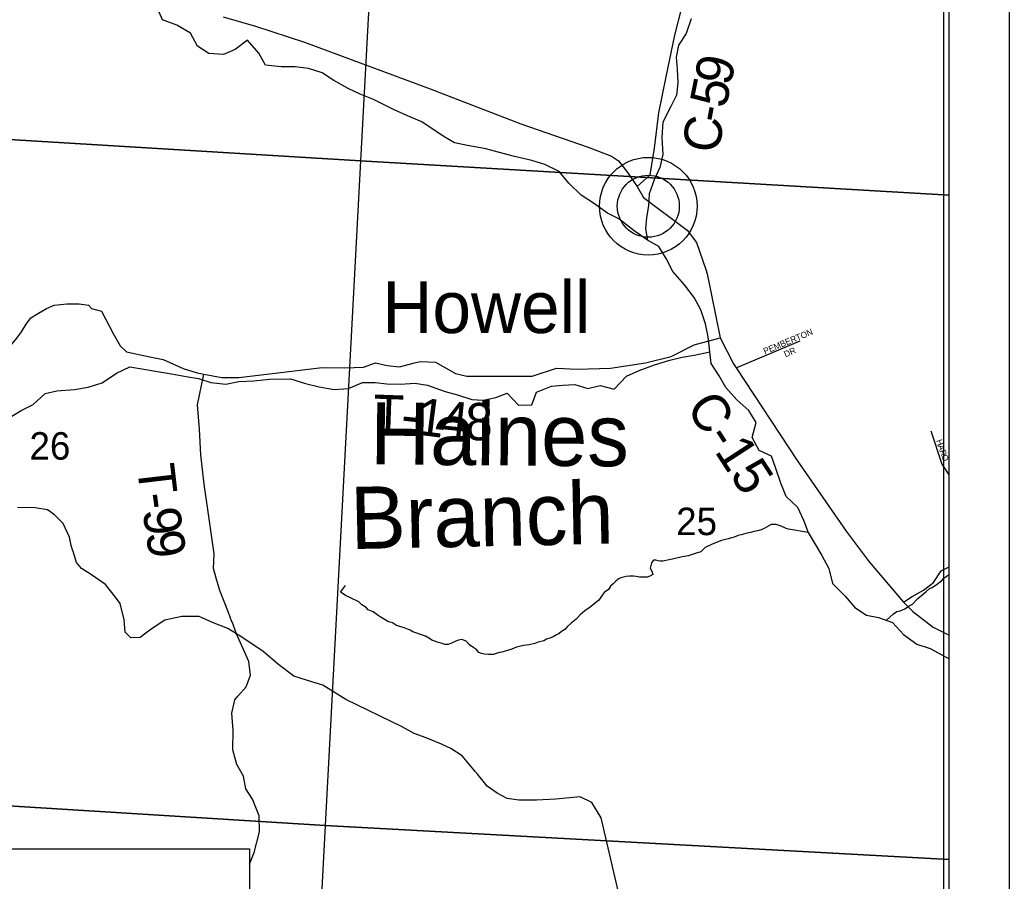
# Model space of a CAD drawing. Extents: x 0 to 34, y 0 to 22.
# Drawn here: x 7.493 to 9, y 16.725 to 18.037 of the extents above; entities that cross this region are included whole.
import ezdxf

# ---------------------------------------------------------------- set-up
doc = ezdxf.new("R2010")
doc.units = 0
for name, color, linetype in [('GM_X_County', 7, 'Continuous'), ('GM_X_County_Road', 7, 'Continuous'), ('GM_X_County_Road_Text', 7, 'Continuous'), ('GM_X_Minor_River', 7, 'Continuous'), ('GM_X_Minor_River_Text', 7, 'Continuous'), ('GM_X_Section', 7, 'Continuous'), ('GM_X_Section_Text', 7, 'Continuous'), ('GM_X_Township', 7, 'Continuous'), ('GM_X_Township_Road', 7, 'Continuous'), ('GM_X_Township_Road_Text', 7, 'Continuous'), ('GM_X_Township_ROW', 7, 'Continuous'), ('GM_X_Township_Subdivision', 7, 'Continuous'), ('GM_X_Township_Subdivision_Text', 7, 'Continuous'), ('GM_X_Unincorporated', 7, 'Continuous'), ('GM_X_Unincorporated_Location', 7, 'Continuous'), ('GM_X_Unincorporated_Text', 7, 'Continuous'), ('SH_Data', 7, 'Continuous'), ('SH_Text', 7, 'Continuous')]:
    doc.layers.add(name, color=color, linetype=linetype)

msp = doc.modelspace()

# ---------------------------------------------------------------- linework, layer by layer
at = {"layer": 'GM_X_County'}
msp.add_lwpolyline([(8.9084, 15.63), (8.9084, 20.8908), (2.1084, 20.8908), (2.1084, 19.9847)], dxfattribs=at)
at = {"layer": 'GM_X_County_Road'}
for points in [[(8.4331, 17.7828), (8.4533, 17.8008), (8.4598, 17.8414), (8.4662, 17.895), (8.4776, 17.9502), (8.4905, 18.0135), (8.5019, 18.0573)], [(7.8026, 18.0416), (7.8521, 18.0274), (7.9265, 18.0026), (8.1178, 17.9317), (8.256, 17.8785), (8.3587, 17.843), (8.3941, 17.8289), (8.4047, 17.8218), (8.4189, 17.804), (8.4222, 17.7991), (8.4331, 17.7828), (8.4431, 17.7661), (8.5093, 17.7164), (8.5235, 17.6974), (8.5378, 17.6565), (8.54, 17.65), (8.5595, 17.5525)], [(8.5595, 17.5525), (8.5802, 17.5127), (8.5843, 17.5065), (8.6772, 17.3658), (8.7517, 17.258), (8.7867, 17.2113), (8.8392, 17.1498), (8.8533, 17.1354), (8.8844, 17.1119), (8.9084, 17.0997)]]:
    msp.add_lwpolyline(points, dxfattribs=at)
at = {"layer": 'GM_X_Minor_River'}
for points in [[(8.6774, 17.2946), (8.6604, 17.3107), (8.6521, 17.3313), (8.6439, 17.3549), (8.6379, 17.3724), (8.619, 17.3808), (8.6085, 17.4007), (8.6146, 17.4235), (8.6033, 17.4418), (8.5852, 17.4578), (8.5686, 17.4769), (8.5581, 17.4944), (8.546, 17.5135), (8.5438, 17.531), (8.5417, 17.5538), (8.5372, 17.5736), (8.5305, 17.5949), (8.5199, 17.614), (8.5056, 17.6331), (8.4875, 17.6537), (8.4777, 17.6735), (8.4665, 17.6918), (8.4491, 17.701), (8.4287, 17.7155), (8.4053, 17.7338), (8.3879, 17.7422), (8.3668, 17.7575), (8.3479, 17.7698), (8.329, 17.7881), (8.3147, 17.8056), (8.2928, 17.8163), (8.2731, 17.8225), (8.2466, 17.8287), (8.2292, 17.8333), (8.2027, 17.8402), (8.1725, 17.8457), (8.1551, 17.8495), (8.1377, 17.8595), (8.1052, 17.8816), (8.0833, 17.8908), (8.0621, 17.9), (8.0319, 17.9154), (8.0115, 17.9238), (7.9933, 17.9322), (7.9714, 17.9445), (7.9533, 17.9559), (7.9329, 17.9628), (7.9124, 17.9652), (7.8912, 17.9653), (7.867, 17.9676), (7.8572, 17.9859), (7.8399, 18.0057), (7.8209, 17.9914), (7.8034, 17.9838), (7.7807, 17.9854), (7.7634, 17.9969), (7.7528, 18.0167), (7.7324, 18.0289), (7.7105, 18.0366), (7.7, 18.0602)], [(8.5156, 18.0382), (8.5079, 18.0162), (8.4965, 17.998), (8.4926, 17.9798), (8.494, 17.9616), (8.4955, 17.941), (8.4931, 17.922), (8.4847, 17.9046), (8.4725, 17.8811), (8.4709, 17.8575), (8.4723, 17.8317), (8.4677, 17.8119), (8.4593, 17.7929), (8.4516, 17.7717), (8.4508, 17.7534), (8.4477, 17.7359), (8.4461, 17.7185), (8.4491, 17.701)], [(7.4718, 17.4276), (7.4953, 17.442), (7.5135, 17.4511), (7.5318, 17.4677), (7.5492, 17.4715), (7.5765, 17.4736), (7.5969, 17.4774), (7.6182, 17.4841), (7.6402, 17.4985), (7.6607, 17.5083), (7.7242, 17.4975), (7.7462, 17.4936), (7.7651, 17.4905), (7.784, 17.4843), (7.8067, 17.482), (7.8264, 17.4857), (7.8492, 17.4871), (7.8734, 17.4893), (7.9052, 17.49), (7.9279, 17.483), (7.9491, 17.4776), (7.9718, 17.4737), (7.9938, 17.4752), (8.015, 17.4842), (8.034, 17.4842), (8.0521, 17.4826), (8.0726, 17.4817), (8.0945, 17.4832), (8.1142, 17.4801), (8.1407, 17.4709), (8.1596, 17.4655), (8.1815, 17.4585), (8.199, 17.4577), (8.2179, 17.4614), (8.2353, 17.4682), (8.2527, 17.4499), (8.2731, 17.4506), (8.28, 17.4696), (8.3028, 17.4786), (8.3202, 17.4801), (8.3384, 17.4815), (8.3581, 17.4754), (8.377, 17.4799), (8.3982, 17.4745), (8.4172, 17.4942), (8.4362, 17.5025), (8.4597, 17.5115), (8.4832, 17.5183), (8.5021, 17.5228), (8.5203, 17.5258), (8.5438, 17.531), (8.5423, 17.5302)], [(8.6774, 17.2946), (8.6869, 17.2748), (8.6936, 17.2558), (8.7148, 17.2208), (8.7254, 17.201), (8.7306, 17.1782), (8.7503, 17.1592), (8.7647, 17.1417), (8.7828, 17.1302), (8.801, 17.1264), (8.8222, 17.1188), (8.8388, 17.1005), (8.8592, 17.0861), (8.8796, 17.0792), (8.9038, 17.0663), (8.9084, 17.0636)], [(8.6936, 17.2558), (8.6637, 17.261), (8.6604, 17.2622), (8.6525, 17.2657), (8.6449, 17.2681), (8.6374, 17.2679), (8.627, 17.262), (8.6224, 17.2601), (8.6164, 17.2587), (8.6114, 17.2573), (8.6057, 17.2559), (8.5989, 17.2544), (8.5916, 17.2523), (8.5874, 17.2512), (8.5813, 17.249), (8.5775, 17.2476), (8.5718, 17.2465), (8.5657, 17.2447), (8.5619, 17.2437), (8.5551, 17.2411), (8.5467, 17.2378), (8.5368, 17.233), (8.5302, 17.2267), (8.5218, 17.2238), (8.5157, 17.222), (8.5115, 17.2205), (8.502, 17.2188), (8.4979, 17.2177), (8.4914, 17.2163), (8.4872, 17.2152), (8.4823, 17.2142), (8.4724, 17.2125), (8.4686, 17.2125), (8.4652, 17.213), (8.4618, 17.2138), (8.4584, 17.2138), (8.4553, 17.2097), (8.4541, 17.2055), (8.4533, 17.2014), (8.4558, 17.1971), (8.4573, 17.1922), (8.4527, 17.1892), (8.4485, 17.1881), (8.4443, 17.1878), (8.4371, 17.1879), (8.4318, 17.1888), (8.4277, 17.1892), (8.4216, 17.1893), (8.4167, 17.1887), (8.4083, 17.1869), (8.4045, 17.1847), (8.401, 17.1817), (8.3968, 17.1776), (8.3926, 17.1742), (8.3894, 17.1693), (8.3833, 17.1645), (8.3798, 17.1604), (8.3748, 17.1528), (8.3617, 17.1424), (8.3537, 17.1364), (8.3467, 17.1305), (8.3402, 17.1241), (8.3329, 17.1178), (8.3267, 17.1122), (8.3232, 17.108), (8.3179, 17.1051), (8.314, 17.1017), (8.3102, 17.1003), (8.3056, 17.0969), (8.3018, 17.0955), (8.2953, 17.0937), (8.2911, 17.0911), (8.2824, 17.0889), (8.2774, 17.0867), (8.2687, 17.085), (8.2645, 17.0843), (8.26, 17.084), (8.2535, 17.0822), (8.2497, 17.0811), (8.2462, 17.08), (8.2424, 17.0782), (8.2272, 17.0739), (8.2238, 17.0732), (8.2185, 17.0718), (8.2143, 17.0703), (8.2071, 17.0701), (8.2006, 17.0705), (8.1961, 17.0714), (8.192, 17.0734), (8.1879, 17.078), (8.1845, 17.0803), (8.1781, 17.0846), (8.1729, 17.0904), (8.1662, 17.0928), (8.1612, 17.0918), (8.157, 17.0903), (8.1505, 17.0874), (8.1452, 17.0856), (8.1403, 17.0853), (8.1346, 17.0873), (8.1286, 17.0889)], [(8.8131, 17.1223), (8.824, 17.1319), (8.829, 17.1356), (8.8339, 17.1366), (8.8408, 17.1399), (8.8477, 17.1444), (8.8527, 17.1466), (8.8608, 17.1556), (8.8696, 17.1627), (8.8735, 17.166), (8.8788, 17.1705), (8.8826, 17.172), (8.8907, 17.1775), (8.8968, 17.1824), (8.9003, 17.1865), (8.9076, 17.1917), (8.9084, 17.1924)], [(8.1286, 17.0889), (8.1252, 17.0905), (8.1207, 17.0921), (8.117, 17.0944), (8.111, 17.098), (8.1034, 17.1004), (8.0963, 17.1032), (8.0914, 17.1048), (8.0876, 17.1071), (8.0827, 17.1091), (8.0771, 17.1111), (8.0665, 17.1143), (8.0606, 17.1182), (8.0568, 17.1194), (8.0534, 17.1206), (8.0493, 17.123), (8.0421, 17.1273), (8.0388, 17.1293), (8.0313, 17.1351), (8.0238, 17.1383), (8.0204, 17.1417), (8.0137, 17.1457), (8.0092, 17.1503), (7.9968, 17.1566), (7.9893, 17.1602), (7.9856, 17.1625), (7.9814, 17.1649), (7.9892, 17.1754)]]:
    msp.add_lwpolyline(points, dxfattribs=at)
at = {"layer": 'GM_X_Section'}
for p, q in [((8.9084, 17.7699), (8.9084, 18.7841)), ((8.9084, 16.7577), (8.9084, 17.7699)), ((8.9084, 15.7545), (8.9084, 16.7577))]:
    msp.add_line(p, q, dxfattribs=at)
for points in [[(6.9681, 18.8952), (8.0664, 18.8297), (8.012, 17.8219), (6.9079, 17.8893)], [(8.012, 17.8219), (7.9583, 16.8099), (6.8455, 16.8788), (6.9079, 17.8893)]]:
    msp.add_lwpolyline(points, close=True, dxfattribs=at)
for points in [[(8.9084, 18.7841), (8.0664, 18.8297), (8.012, 17.8219), (8.9084, 17.7699)], [(8.9084, 17.7699), (8.012, 17.8219), (7.9583, 16.8099), (8.9084, 16.7577)], [(6.8391, 16.7743), (6.8455, 16.8788), (7.9583, 16.8099), (7.9053, 15.8044), (6.7831, 15.8661), (6.795, 16.0591)], [(8.9084, 16.7577), (7.9583, 16.8099), (7.9053, 15.8044), (8.9084, 15.7545)]]:
    msp.add_lwpolyline(points, dxfattribs=at)
at = {"layer": 'GM_X_Township'}
msp.add_lwpolyline([(8.9084, 15.63), (8.9084, 20.8908), (5.9855, 20.8908)], dxfattribs=at)
at = {"layer": 'GM_X_Township_Road'}
for points in [[(7.8987, 17.5006), (7.9536, 17.5074), (7.9881, 17.5066), (8.0165, 17.5077), (8.0346, 17.5145), (8.0524, 17.5104), (8.0714, 17.5084), (8.0922, 17.5138), (8.1028, 17.5164), (8.1263, 17.5156), (8.1566, 17.4981), (8.174, 17.4943), (8.2733, 17.4939), (8.3104, 17.5061), (8.3418, 17.5049), (8.3926, 17.5064), (8.446, 17.5144), (8.485, 17.5239), (8.5202, 17.5417), (8.5595, 17.5525)], [(7.8161, 17.1201), (7.8108, 17.1343), (7.7979, 17.1674), (7.7923, 17.1864), (7.7881, 17.2012), (7.7892, 17.2233), (7.7809, 17.2804), (7.7737, 17.3298), (7.7688, 17.3743), (7.7665, 17.4135), (7.7638, 17.4504), (7.7733, 17.4972)], [(7.5739, 17.2281), (7.5714, 17.2363), (7.5688, 17.2489), (7.5589, 17.2694), (7.546, 17.2827), (7.535, 17.2904), (7.5165, 17.2934), (7.4896, 17.2938)], [(8.8392, 17.1498), (8.8524, 17.1586), (8.8695, 17.1681), (8.8782, 17.1746), (8.8846, 17.18), (8.8963, 17.1975), (8.9084, 17.2035)], [(7.8252, 17.0066), (7.8253, 17.0068), (7.8377, 17.0209), (7.8445, 17.0388), (7.8419, 17.0593), (7.823, 17.1018), (7.8162, 17.1198), (7.8161, 17.1201)], [(7.8426, 16.7509), (7.8499, 16.7683), (7.8582, 16.7999), (7.8578, 16.8246), (7.8472, 16.8497), (7.8374, 16.8657), (7.8339, 16.8847), (7.8237, 16.9026), (7.8177, 16.925), (7.818, 16.9543), (7.8158, 16.9806), (7.8203, 17.0011), (7.8252, 17.0066)], [(8.4101, 16.6863), (8.3786, 16.8213), (8.3642, 16.8445), (8.3464, 16.8533), (8.3093, 16.8499), (8.2798, 16.8484), (8.2533, 16.848), (8.2355, 16.851), (8.2199, 16.8587), (8.2048, 16.8697), (8.1904, 16.8872), (8.1865, 16.8919), (8.1843, 16.8946)]]:
    msp.add_lwpolyline(points, dxfattribs=at)
at = {"layer": 'GM_X_Township_ROW'}
for points in [[(7.3077, 17.4886), (7.3126, 17.4878), (7.3221, 17.483), (7.3363, 17.4783), (7.3886, 17.4783), (7.4052, 17.4831), (7.4195, 17.4902), (7.4313, 17.495), (7.448, 17.5069), (7.4612, 17.52), (7.4622, 17.5211), (7.4789, 17.5402), (7.4884, 17.5521), (7.4955, 17.5616), (7.5026, 17.5735), (7.5097, 17.583), (7.5216, 17.5901), (7.5335, 17.5973), (7.5454, 17.602), (7.5644, 17.6044), (7.5747, 17.6044)], [(7.5747, 17.6044), (7.5834, 17.6044), (7.5976, 17.602), (7.6024, 17.5973), (7.6172, 17.593), (7.6354, 17.5592), (7.646, 17.5402), (7.6555, 17.5311), (7.6695, 17.528), (7.6911, 17.5234), (7.7115, 17.5192), (7.7418, 17.5059), (7.7631, 17.4991), (7.7733, 17.4972), (7.8009, 17.4918), (7.8267, 17.4918), (7.8987, 17.5006)], [(8.1843, 16.8946), (8.1794, 16.9005), (8.1669, 16.9157), (8.1495, 16.9268), (8.1355, 16.9336), (8.112, 16.9432), (8.0934, 16.95), (8.0756, 16.9599), (7.9896, 17.0018), (7.9544, 17.0235), (7.9313, 17.0304), (7.9104, 17.0372), (7.8877, 17.0543), (7.8635, 17.0745), (7.8267, 17.0996), (7.823, 17.1018), (7.8097, 17.1095), (7.7866, 17.1187), (7.7661, 17.1282), (7.74, 17.1282), (7.7138, 17.1225), (7.693, 17.1088), (7.6847, 17.1028), (7.6763, 17.0959), (7.6623, 17.0955), (7.6536, 17.1039), (7.6521, 17.1229), (7.6457, 17.148), (7.6388, 17.1576), (7.6233, 17.1766), (7.6021, 17.1914), (7.5869, 17.2013), (7.5794, 17.2101), (7.5743, 17.2269), (7.5739, 17.2281)]]:
    msp.add_lwpolyline(points, dxfattribs=at)
at = {"layer": 'GM_X_Township_Subdivision'}
for points in [[(8.5843, 17.5065), (8.6816, 17.5479)], [(8.9009, 17.3554), (8.9007, 17.3556), (8.8981, 17.3595), (8.8812, 17.4102)], [(8.9084, 17.3438), (8.9009, 17.3554)]]:
    msp.add_lwpolyline(points, dxfattribs=at)
at = {"layer": 'GM_X_Unincorporated'}
for radius in [0.0744, 0.0472]:
    msp.add_circle((8.4503, 17.7529), radius, dxfattribs=at)
at = {"layer": 'GM_X_Unincorporated_Location'}
msp.add_line((8.4503, 17.7529), (8.4503, 17.7529), dxfattribs=at)
at = {"layer": 'SH_Data'}
for p, q in [((9, 21), (9, 14)), ((8.9, 20.9), (8.9, 14.1))]:
    msp.add_line(p, q, dxfattribs=at)
at = {"layer": 'SH_Text'}
msp.add_lwpolyline([(6.0532, 16.7743), (7.8426, 16.7743), (7.8426, 16.0591), (6.0532, 16.0591)], close=True, dxfattribs=at)

# ---------------------------------------------------------------- texts
at = {"layer": 'GM_X_County_Road_Text'}
for s, height, rotation, p in [('9', 0.0568, 78.1389, (8.5754, 17.9348)), ('5', 0.0568, 78.5958, (8.5685, 17.9006)), ('-', 0.0568, 79.7983, (8.5644, 17.8779)), ('C', 0.0568, 82.2918, (8.5582, 17.8323)), ('C-15', 0.05682, 303.0238, (8.5066, 17.4468))]:
    msp.add_text(s, height=height, rotation=rotation, dxfattribs=at).set_placement(p)
at = {"layer": 'GM_X_Minor_River_Text'}
for s, rotation, p in [('Haines', 359.5508, (8.0263, 17.3597)), ('Branch', 1.2147, (7.9972, 17.2306))]:
    msp.add_text(s, height=0.09469, rotation=rotation, dxfattribs=at).set_placement(p)
at = {"layer": 'GM_X_Section_Text'}
for s, p in [('26', (7.5077, 17.3669)), ('25', (8.4927, 17.2519))]:
    msp.add_text(s, height=0.04186, rotation=0, dxfattribs=at).set_placement(p)
at = {"layer": 'GM_X_Township_Road_Text'}
for s, rotation, p in [('T', 357.9714, (8.0305, 17.4094)), ('1', 352.6917, (8.0948, 17.4055)), ('4', 354.1461, (8.1311, 17.4009)), ('8', 358.4968, (8.1706, 17.397)), ('-', 353.7958, (8.0719, 17.408)), ('T', 276.6663, (7.6713, 17.3573)), ('-', 277.9144, (7.6765, 17.3137)), ('9', 278.4253, (7.6797, 17.2901)), ('9', 277.9249, (7.6849, 17.2556))]:
    msp.add_text(s, height=0.0568, rotation=rotation, dxfattribs=at).set_placement(p)
at = {"layer": 'GM_X_Township_Subdivision_Text'}
for s, rotation, p in [('PEMBERTON', 22.5671, (8.6279, 17.5272)), ('DR', 23.9616, (8.6594, 17.5225)), ('H', 288.4342, (8.8883, 17.396)), ('A', 288.4342, (8.891, 17.3881)), ('R', 288.4342, (8.8936, 17.3802)), ('O', 291.1457, (8.8961, 17.3726))]:
    msp.add_text(s, height=0.00947, rotation=rotation, dxfattribs=at).set_placement(p)
at = {"layer": 'GM_X_Unincorporated_Text'}
msp.add_text('Howell', height=0.07898, rotation=0, dxfattribs=at).set_placement((8.0452, 17.5597))

doc.saveas('drawing.dxf')
